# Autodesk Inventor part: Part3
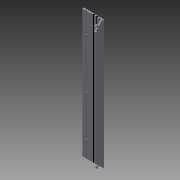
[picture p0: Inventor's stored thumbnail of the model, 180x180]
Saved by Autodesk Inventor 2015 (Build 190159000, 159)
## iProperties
Created: 2018-03
Part Number: Part3
Material: Generic
Document SubType Name: Modeling
Designer: maxzh
Density: 1 g/cm^3
Appearance: Default
Author: maxzh
Title: C:\Users\maxzh\Desktop\USBP\03.01.2018\STEP\Part3.stp
Creation Date: 2018-03-01
Sending System: Autodesk Inventor 2015
Preprocessor: ST-DEVELOPER v15.6
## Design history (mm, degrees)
node "Part31"
body "Solid1"
node "Solid1_1"
node "Solid1_2"
body "Solid2"
node "Solid2_1"
node "Base1"
node "Base2"
node "Base3"
node "Base4"
node "Base5"
